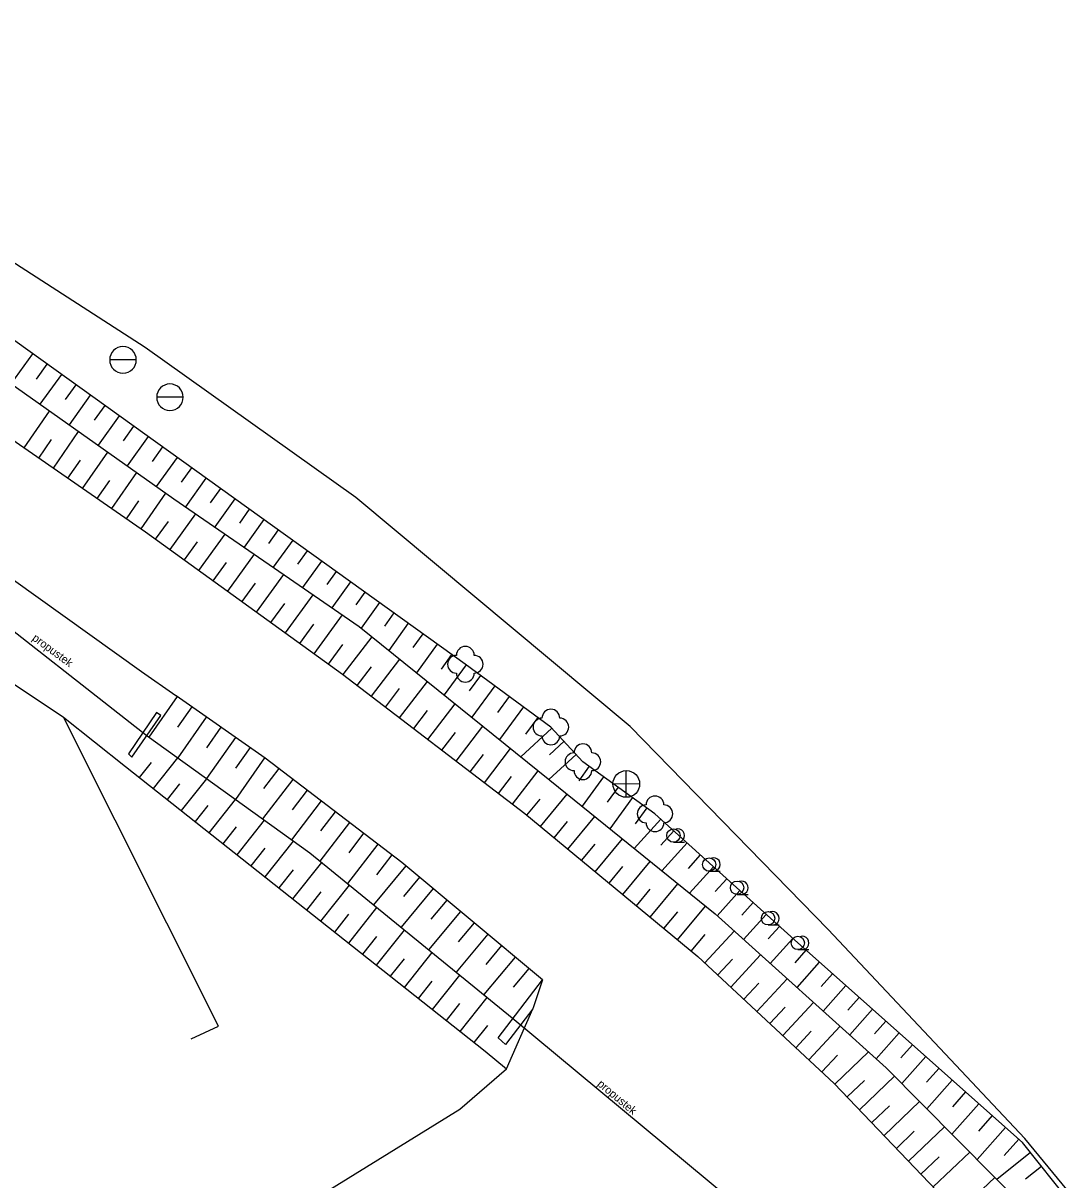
# Model space of a CAD drawing. Extents: x -747135 to -746147, y -1093269 to -1091735.
# Drawn here: x -746783.5 to -746724.8, y -1092415.2 to -1092350.2 of the extents above; entities that cross this region are included whole.
import ezdxf

# ---------------------------------------------------------------- set-up
doc = ezdxf.new("R2010")
doc.units = 0
for name, color, linetype in [('101', 7, 'Continuous'), ('1016', 7, 'Continuous'), ('1029', 7, 'Continuous'), ('105', 7, 'Continuous'), ('23700', 7, 'Continuous'), ('305', 7, 'Continuous'), ('316', 7, 'Continuous'), ('424', 7, 'Continuous'), ('803', 7, 'Continuous')]:
    doc.layers.add(name, color=color, linetype=linetype)

msp = doc.modelspace()

# ---------------------------------------------------------------- linework, layer by layer
at = {"layer": '101'}
for points in [[(-746676.31, -1092494.93), (-746679.28, -1092488.1), (-746684.61, -1092481.19), (-746692.58, -1092466.75), (-746703.9, -1092446.01), (-746716.46, -1092426.76), (-746727.325, -1092413.107), (-746739.95, -1092401.9), (-746747.98, -1092394.64), (-746752.03, -1092391.71), (-746753.83, -1092389.76), (-746758.64, -1092386.23), (-746765.82, -1092381.07), (-746787.5, -1092365.52), (-746806.41, -1092354.03)], [(-746807.12, -1092355.24), (-746796.58, -1092362.79), (-746786.63, -1092368.73), (-746775.02, -1092376.93), (-746764.6, -1092384.11), (-746753.89, -1092392.74), (-746744.6, -1092400.27), (-746734.99, -1092408.91), (-746726.93, -1092417.05), (-746720.19, -1092425.45), (-746712.76, -1092435.88), (-746705, -1092448.32), (-746698.55, -1092460.04), (-746691.76, -1092472.37), (-746682.53, -1092488.74), (-746678.42, -1092495.91)], [(-746782.968, -1092368.771), (-746784.18, -1092370.461)], [(-746782.155, -1092369.354), (-746782.759, -1092370.196)], [(-746781.343, -1092369.936), (-746782.546, -1092371.614)], [(-746780.53, -1092370.519), (-746781.13, -1092371.355)], [(-746779.717, -1092371.102), (-746780.912, -1092372.768)], [(-746778.905, -1092371.685), (-746779.5, -1092372.515)], [(-746783.44, -1092374.067), (-746782.008, -1092371.994)], [(-746778.092, -1092372.268), (-746779.279, -1092373.922)], [(-746777.28, -1092372.851), (-746777.871, -1092373.675)], [(-746782.618, -1092374.635), (-746781.904, -1092373.603)], [(-746781.795, -1092375.204), (-746780.374, -1092373.148)], [(-746776.467, -1092373.433), (-746777.645, -1092375.076)], [(-746780.15, -1092376.341), (-746778.741, -1092374.302)], [(-746775.654, -1092374.016), (-746776.241, -1092374.835)], [(-746780.972, -1092375.772), (-746780.265, -1092374.749)], [(-746774.842, -1092374.599), (-746776.011, -1092376.23)], [(-746778.504, -1092377.478), (-746777.107, -1092375.456)], [(-746774.029, -1092375.182), (-746774.612, -1092375.994)], [(-746779.327, -1092376.909), (-746778.625, -1092375.894)], [(-746773.217, -1092375.765), (-746774.372, -1092377.376)], [(-746776.859, -1092378.615), (-746775.473, -1092376.61)], [(-746772.404, -1092376.348), (-746772.976, -1092377.146)], [(-746771.591, -1092376.93), (-746772.725, -1092378.511)], [(-746777.682, -1092378.046), (-746776.986, -1092377.04)], [(-746770.779, -1092377.513), (-746771.34, -1092378.296)], [(-746776.045, -1092379.196), (-746775.328, -1092378.204)], [(-746775.235, -1092379.782), (-746773.787, -1092377.779)], [(-746769.966, -1092378.096), (-746771.078, -1092379.646)], [(-746773.614, -1092380.953), (-746772.14, -1092378.915)], [(-746769.154, -1092378.679), (-746769.704, -1092379.446)], [(-746774.424, -1092380.367), (-746773.694, -1092379.357)], [(-746768.341, -1092379.262), (-746769.431, -1092380.781)], [(-746771.993, -1092382.125), (-746770.493, -1092380.05)], [(-746767.528, -1092379.845), (-746768.068, -1092380.597)], [(-746772.803, -1092381.539), (-746772.06, -1092380.511)], [(-746766.716, -1092380.427), (-746767.784, -1092381.916)], [(-746770.372, -1092383.297), (-746768.845, -1092381.185)], [(-746765.903, -1092381.01), (-746766.432, -1092381.747)], [(-746771.182, -1092382.711), (-746770.426, -1092381.664)], [(-746765.091, -1092381.594), (-746766.138, -1092383.05)], [(-746769.562, -1092383.883), (-746768.792, -1092382.817)], [(-746768.751, -1092384.468), (-746767.198, -1092382.32)], [(-746764.279, -1092382.177), (-746764.797, -1092382.898)], [(-746763.467, -1092382.761), (-746764.496, -1092384.193)], [(-746767.13, -1092385.64), (-746765.551, -1092383.455)], [(-746762.655, -1092383.345), (-746763.186, -1092384.083)], [(-746767.941, -1092385.054), (-746767.158, -1092383.971)], [(-746761.843, -1092383.928), (-746762.937, -1092385.45)], [(-746765.51, -1092386.813), (-746763.884, -1092384.687)], [(-746761.031, -1092384.512), (-746761.594, -1092385.295)], [(-746766.32, -1092386.226), (-746765.524, -1092385.124)], [(-746760.219, -1092385.095), (-746761.377, -1092386.707)], [(-746763.921, -1092388.028), (-746762.327, -1092385.942)], [(-746759.407, -1092385.679), (-746760.002, -1092386.507)], [(-746764.716, -1092387.42), (-746763.911, -1092386.367)], [(-746758.595, -1092386.263), (-746759.834, -1092387.951)], [(-746762.333, -1092389.242), (-746760.769, -1092387.197)], [(-746757.789, -1092386.855), (-746758.422, -1092387.717)], [(-746763.127, -1092388.635), (-746762.337, -1092387.602)], [(-746756.983, -1092387.446), (-746758.275, -1092389.207)], [(-746774.838, -1092388.05), (-746776.428, -1092390.323)], [(-746774.019, -1092388.623), (-746774.817, -1092389.765)], [(-746760.744, -1092390.457), (-746759.211, -1092388.452)], [(-746756.177, -1092388.038), (-746756.836, -1092388.936)], [(-746755.37, -1092388.63), (-746756.716, -1092390.463)], [(-746773.199, -1092389.196), (-746774.804, -1092391.492)], [(-746761.538, -1092389.85), (-746760.764, -1092388.837)], [(-746754.564, -1092389.221), (-746755.25, -1092390.156)], [(-746772.38, -1092389.769), (-746773.186, -1092390.922)], [(-746759.155, -1092391.672), (-746757.653, -1092389.708)], [(-746753.769, -1092389.826), (-746755.511, -1092391.434)], [(-746776.53, -1092390.25), (-746767.37, -1092396.84), (-746755.999, -1092406.108)], [(-746771.56, -1092390.342), (-746773.181, -1092392.66)], [(-746759.95, -1092391.065), (-746759.191, -1092390.072)], [(-746753.091, -1092390.56), (-746753.908, -1092391.314)], [(-746770.741, -1092390.915), (-746771.555, -1092392.079)], [(-746757.566, -1092392.887), (-746756.095, -1092390.963)], [(-746776.948, -1092392.595), (-746776.28, -1092391.753)], [(-746776.164, -1092393.216), (-746774.8, -1092391.495)], [(-746769.921, -1092391.488), (-746771.557, -1092393.828)], [(-746758.361, -1092392.28), (-746757.618, -1092391.307)], [(-746752.413, -1092391.295), (-746753.937, -1092392.702)], [(-746769.125, -1092392.094), (-746769.983, -1092393.218)], [(-746756.772, -1092393.494), (-746756.044, -1092392.543)], [(-746755.978, -1092394.102), (-746754.537, -1092392.218)], [(-746751.677, -1092391.965), (-746752.263, -1092392.775)], [(-746750.867, -1092392.551), (-746752.07, -1092394.215)], [(-746775.38, -1092393.837), (-746774.684, -1092392.958)], [(-746774.596, -1092394.458), (-746773.175, -1092392.664)], [(-746768.33, -1092392.701), (-746770.03, -1092394.927)], [(-746750.057, -1092393.138), (-746750.674, -1092393.992)], [(-746773.029, -1092395.7), (-746771.549, -1092393.833)], [(-746767.535, -1092393.307), (-746768.376, -1092394.409)], [(-746755.187, -1092394.714), (-746754.438, -1092393.808)], [(-746754.416, -1092395.351), (-746752.913, -1092393.532)], [(-746749.246, -1092393.724), (-746750.514, -1092395.476)], [(-746773.812, -1092395.079), (-746773.087, -1092394.164)], [(-746766.741, -1092393.914), (-746768.405, -1092396.095)], [(-746765.946, -1092394.521), (-746766.77, -1092395.6)], [(-746748.436, -1092394.31), (-746749.086, -1092395.208)], [(-746771.461, -1092396.942), (-746769.924, -1092395.002)], [(-746765.151, -1092395.128), (-746766.808, -1092397.298)], [(-746753.645, -1092395.988), (-746752.891, -1092395.075)], [(-746752.874, -1092396.625), (-746751.359, -1092394.791)], [(-746747.656, -1092394.933), (-746749.148, -1092396.583)], [(-746772.245, -1092396.321), (-746771.491, -1092395.37)], [(-746764.356, -1092395.734), (-746765.194, -1092396.832)], [(-746746.914, -1092395.604), (-746747.642, -1092396.409)], [(-746769.893, -1092398.184), (-746768.299, -1092396.172)], [(-746763.561, -1092396.341), (-746765.257, -1092398.562)], [(-746752.103, -1092397.262), (-746751.343, -1092396.341)], [(-746751.332, -1092397.898), (-746749.805, -1092396.051)], [(-746746.172, -1092396.274), (-746747.592, -1092397.845)], [(-746770.677, -1092397.563), (-746769.894, -1092396.575)], [(-746762.766, -1092396.948), (-746763.624, -1092398.071)], [(-746745.431, -1092396.945), (-746746.122, -1092397.71)], [(-746768.326, -1092399.426), (-746766.706, -1092397.381)], [(-746761.979, -1092397.564), (-746763.801, -1092399.749)], [(-746750.561, -1092398.535), (-746749.795, -1092397.608)], [(-746749.791, -1092399.172), (-746748.252, -1092397.31)], [(-746744.689, -1092397.616), (-746746.036, -1092399.106)], [(-746769.11, -1092398.805), (-746768.298, -1092397.781)], [(-746761.211, -1092398.205), (-746762.119, -1092399.293)], [(-746743.947, -1092398.286), (-746744.603, -1092399.011)], [(-746767.542, -1092400.047), (-746766.736, -1092399.03)], [(-746766.758, -1092400.668), (-746765.155, -1092398.645)], [(-746760.443, -1092398.845), (-746762.251, -1092401.012)], [(-746749.02, -1092399.809), (-746748.247, -1092398.875)], [(-746748.249, -1092400.446), (-746746.698, -1092398.57)], [(-746743.205, -1092398.957), (-746744.486, -1092400.373)], [(-746759.675, -1092399.486), (-746760.575, -1092400.565)], [(-746742.464, -1092399.628), (-746743.103, -1092400.335)], [(-746765.974, -1092401.289), (-746765.177, -1092400.283)], [(-746765.191, -1092401.91), (-746763.605, -1092399.909)], [(-746758.907, -1092400.127), (-746760.7, -1092402.276)], [(-746747.478, -1092401.083), (-746746.7, -1092400.141)], [(-746746.707, -1092401.72), (-746745.144, -1092399.829)], [(-746741.722, -1092400.298), (-746742.998, -1092401.71)], [(-746758.14, -1092400.767), (-746759.032, -1092401.837)], [(-746740.98, -1092400.969), (-746741.617, -1092401.674)], [(-746764.407, -1092402.531), (-746763.618, -1092401.536)], [(-746763.623, -1092403.152), (-746762.054, -1092401.172)], [(-746757.372, -1092401.408), (-746759.15, -1092403.54)], [(-746745.936, -1092402.357), (-746745.157, -1092401.414)], [(-746745.186, -1092403.018), (-746743.527, -1092401.235)], [(-746740.238, -1092401.639), (-746741.511, -1092403.047)], [(-746756.604, -1092402.048), (-746757.489, -1092403.11)], [(-746739.493, -1092402.306), (-746740.124, -1092403.017)], [(-746762.839, -1092403.773), (-746762.059, -1092402.789)], [(-746762.055, -1092404.394), (-746760.504, -1092402.436)], [(-746755.836, -1092402.689), (-746757.6, -1092404.803)], [(-746744.454, -1092403.699), (-746743.618, -1092402.801)], [(-746743.722, -1092404.38), (-746742.039, -1092402.572)], [(-746738.745, -1092402.97), (-746740.011, -1092404.396)], [(-746755.068, -1092403.329), (-746755.946, -1092404.382)], [(-746761.272, -1092405.015), (-746760.5, -1092404.042)], [(-746760.488, -1092405.636), (-746758.953, -1092403.7)], [(-746742.99, -1092405.062), (-746742.143, -1092404.151)], [(-746742.258, -1092405.743), (-746740.552, -1092403.91)], [(-746737.997, -1092403.634), (-746738.632, -1092404.349)], [(-746737.249, -1092404.298), (-746738.523, -1092405.733)], [(-746759.704, -1092406.257), (-746758.941, -1092405.295)], [(-746758.92, -1092406.878), (-746757.403, -1092404.963)], [(-746741.526, -1092406.424), (-746740.667, -1092405.501)], [(-746740.794, -1092407.106), (-746739.064, -1092405.247)], [(-746736.501, -1092404.961), (-746737.141, -1092405.682)], [(-746735.753, -1092405.625), (-746737.036, -1092407.07)], [(-746758.136, -1092407.499), (-746757.382, -1092406.547)], [(-746740.062, -1092407.787), (-746739.191, -1092406.851)], [(-746739.33, -1092408.468), (-746737.577, -1092406.585)], [(-746735.006, -1092406.289), (-746735.649, -1092407.014)], [(-746734.258, -1092406.953), (-746735.549, -1092408.408)], [(-746737.868, -1092409.833), (-746735.976, -1092408.023)], [(-746733.51, -1092407.617), (-746734.162, -1092408.352)], [(-746738.598, -1092409.15), (-746737.715, -1092408.201)], [(-746732.762, -1092408.281), (-746734.11, -1092409.799)], [(-746736.486, -1092411.279), (-746734.513, -1092409.391)], [(-746732.014, -1092408.945), (-746732.709, -1092409.728)], [(-746737.177, -1092410.556), (-746736.204, -1092409.625)], [(-746731.266, -1092409.608), (-746732.7, -1092411.223)], [(-746730.518, -1092410.272), (-746731.256, -1092411.104)], [(-746735.795, -1092412.001), (-746734.802, -1092411.052)], [(-746735.103, -1092412.724), (-746733.106, -1092410.813)], [(-746729.771, -1092410.936), (-746731.289, -1092412.647)], [(-746729.023, -1092411.6), (-746729.804, -1092412.48)], [(-746734.412, -1092413.446), (-746733.407, -1092412.485)], [(-746733.721, -1092414.169), (-746731.698, -1092412.234)], [(-746728.275, -1092412.264), (-746729.879, -1092414.071)], [(-746727.527, -1092412.928), (-746728.351, -1092413.856)], [(-746733.029, -1092414.891), (-746732.012, -1092413.918)], [(-746732.338, -1092415.614), (-746730.291, -1092413.656)], [(-746726.87, -1092413.678), (-746728.771, -1092415.191)], [(-746726.248, -1092414.461), (-746727.156, -1092415.183)], [(-746730.956, -1092417.059), (-746728.884, -1092415.077)]]:
    msp.add_lwpolyline(points, dxfattribs=at)
at = {"layer": '1016'}
for points in [[(-746808.227, -1092357.17), (-746797.53, -1092364.29), (-746787.69, -1092371.13), (-746776.62, -1092378.78), (-746765.54, -1092386.79), (-746755.3, -1092394.62), (-746745.57, -1092402.66), (-746737.91, -1092409.79), (-746728.85, -1092419.26), (-746722.7, -1092426.86), (-746714.67, -1092437.95), (-746707.62, -1092449.35), (-746700.44, -1092461.3), (-746693.84, -1092472.82), (-746684.01, -1092490.2), (-746680.08, -1092497.02)], [(-746774.902, -1092388.005), (-746776.84, -1092386.65), (-746785.57, -1092380.41), (-746796.49, -1092372.78), (-746811.92, -1092362.41), (-746816.377, -1092359.347)], [(-746754.3, -1092403.97), (-746762.2, -1092397.38), (-746769.89, -1092391.51), (-746774.898, -1092388.008)], [(-746781.22, -1092389.21), (-746777.733, -1092391.973)], [(-746777.39, -1092391.45), (-746775.75, -1092389.12), (-746775.998, -1092388.951), (-746777.569, -1092391.269), (-746777.39, -1092391.45)], [(-746777.731, -1092391.974), (-746757.53, -1092407.98)], [(-746754.84, -1092405.61), (-746756.38, -1092407.6), (-746756.79, -1092407.24), (-746754.3, -1092403.97)], [(-746754.3, -1092403.97), (-746754.84, -1092405.61)], [(-746768.8, -1092417.34), (-746758.94, -1092411.24), (-746756.32, -1092408.98), (-746754.84, -1092405.61)], [(-746757.53, -1092407.98), (-746756.32, -1092408.98)]]:
    msp.add_lwpolyline(points, dxfattribs=at)
at = {"layer": '1029'}
for p, q in [((-746746.94, -1092396.234), (-746746.315, -1092396.234)), ((-746744.933, -1092397.866), (-746744.308, -1092397.866)), ((-746743.368, -1092399.167), (-746742.743, -1092399.167)), ((-746741.626, -1092400.887), (-746741.001, -1092400.887)), ((-746739.95, -1092402.275), (-746739.325, -1092402.275))]:
    msp.add_line(p, q, dxfattribs=at)
for centre in [(-746746.94, -1092395.859), (-746744.933, -1092397.491), (-746743.368, -1092398.792), (-746741.626, -1092400.512), (-746739.95, -1092401.9)]:
    msp.add_circle(centre, 0.375, dxfattribs=at)
for centre in [(-746746.69, -1092395.859), (-746744.683, -1092397.491), (-746743.118, -1092398.792), (-746741.376, -1092400.512), (-746739.7, -1092401.9)]:
    msp.add_arc(centre, 0.375, 249.49437, 109.04743, dxfattribs=at)
at = {"layer": '23700'}
for points in [[(-746786.72, -1092382.28), (-746776.53, -1092390.25)], [(-746756, -1092406.11), (-746742.5, -1092417.34)]]:
    msp.add_lwpolyline(points, dxfattribs=at)
at = {"layer": '305'}
for points in [[(-746786.6, -1092385.62), (-746781.22, -1092389.21)], [(-746774.04, -1092407.29), (-746772.52, -1092406.57)]]:
    msp.add_lwpolyline(points, dxfattribs=at)
at = {"layer": '316'}
for p, q in [((-746777.133, -1092369.12), (-746778.628, -1092369.12)), ((-746774.493, -1092371.22), (-746775.988, -1092371.22)), ((-746749.591, -1092393.708), (-746749.59, -1092392.213)), ((-746748.838, -1092392.966), (-746750.338, -1092392.961))]:
    msp.add_line(p, q, dxfattribs=at)
msp.add_circle((-746749.59, -1092392.96), 0.75, dxfattribs=at)
for centre, start, end in [((-746777.88, -1092369.12), 0, 180), ((-746777.88, -1092369.12), 180, 0), ((-746775.24, -1092371.22), 0, 180), ((-746775.24, -1092371.22), 180, 0)]:
    msp.add_arc(centre, 0.747, start, end, dxfattribs=at)
at = {"layer": '424'}
msp.add_lwpolyline([(-746666.48, -1092509.53), (-746671.18, -1092501.38), (-746679.28, -1092488.1), (-746683.01, -1092480.66), (-746691.02, -1092465.89), (-746695.91, -1092457.38), (-746697.67, -1092451.5), (-746700.29, -1092444.13), (-746704.56, -1092439.88), (-746720.11, -1092421.5), (-746727.2, -1092412.89), (-746738.25, -1092401.15), (-746749.37, -1092389.72), (-746764.79, -1092376.86), (-746776.64, -1092368.43), (-746787.43, -1092361.47), (-746799.53, -1092355.13), (-746817.34, -1092343.1), (-746824.75, -1092337.86), (-746838.2, -1092329.38), (-746851.64, -1092319.28), (-746869.05, -1092306.53), (-746874.05, -1092300.95)], dxfattribs=at)
for centre in [(-746758.64, -1092386.23), (-746753.83, -1092389.76), (-746752.03, -1092391.71), (-746747.98, -1092394.64)]:
    msp.add_circle(centre, 0.0005, dxfattribs=at)
for centre, start, end in [((-746758.64, -1092385.73), 0, 179.99999), ((-746759.14, -1092386.23), 89.99999, 269.99999), ((-746758.14, -1092386.23), 270, 89.99999), ((-746758.64, -1092386.73), 179.99999, 359.99999), ((-746754.33, -1092389.76), 89.99999, 269.99999), ((-746753.83, -1092389.26), 0, 179.99999), ((-746753.33, -1092389.76), 270, 89.99999), ((-746753.83, -1092390.26), 179.99999, 359.99999), ((-746752.53, -1092391.71), 89.99999, 269.99999), ((-746752.03, -1092391.21), 0, 179.99999), ((-746751.53, -1092391.71), 270, 89.99999), ((-746752.03, -1092392.21), 179.99999, 359.99999), ((-746747.98, -1092394.14), 0, 179.99999), ((-746748.48, -1092394.64), 89.99999, 269.99999), ((-746747.48, -1092394.64), 270, 89.99999), ((-746747.98, -1092395.14), 179.99999, 359.99999)]:
    msp.add_arc(centre, 0.5, start, end, dxfattribs=at)
at = {"layer": '803'}
msp.add_lwpolyline([(-746772.52, -1092406.57), (-746781.22, -1092389.21)], dxfattribs=at)

# ---------------------------------------------------------------- texts
at = {"layer": '105'}
for rotation, p in [(323.56516, (-746783.022, -1092384.842)), (319.87712, (-746751.254, -1092409.885))]:
    msp.add_text('propustek', height=0.45, rotation=rotation, dxfattribs=at).set_placement(p)

doc.saveas('drawing.dxf')
